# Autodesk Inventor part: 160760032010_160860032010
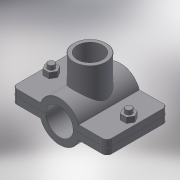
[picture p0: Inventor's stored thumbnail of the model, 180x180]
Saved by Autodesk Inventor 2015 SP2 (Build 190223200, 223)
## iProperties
Created: 2017-05
Part Number: 160760032010_160860032010
Material: Generic
Description: PLASSON SADDLE 32-1"
Document SubType Name: Modeling
Designer: KIM
Density: 1 g/cm^3
Appearance: Default
Author: KIM
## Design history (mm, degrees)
derived "16076.ipt"
feature "Solid1::16076.ipt"
feature "Solid2::16076.ipt"
tag "TaggingFeature1"
body "Solid1"
other parameters: "d0" = 48, "d1" = 92, "d2" = 16, "d3" = 32, "d5" = 0, "d6" = 4.6, "d7" = 92, "d8" = 0.1, "d10" = 0, "d11" = 0.32, "d14" = 39.3783, "d20" = 0.32, "d23" = 0.32, "d37" = 8, "d38" = 24, "d39" = 0, "d40" = 3, "d41" = 5, "d42" = 0, "d43" = 6, "d44" = 3, "d45" = 0, "d46" = 0.32, "d51" = 42, "d52" = 30.291, "d53" = 21, "d54" = 0, "d57" = 0, "d58" = 34.56, "d60" = 0, "d66" = 0, "d_" = 32, "G_" = 30.291, "A_" = 42, "L_" = 92, "l_2" = 21
